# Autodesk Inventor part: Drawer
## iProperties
Created: 2006-01
Part Number: Drawer
Document SubType Name: Modeling
Designer: Martin
Material: Wood_Pine
d22: 650,000 mm
d0: 600,000 mm
d1: 500,000 mm
Width: 600,000 mm
Draw_Height: 100,000 mm
d2: 100,000 mm
Author: Martin
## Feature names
1. Extrusion1
2. Shell1
3. Extrusion2
4. Hole1
5. Hole2
